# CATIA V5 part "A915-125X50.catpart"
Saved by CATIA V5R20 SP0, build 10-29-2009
Part number: A915-125X50
Source: Unknown
Property "A": "75.000"
Property "ARTICLENO": "A915-125X50"
Property "BOMINFO": "A915-125X50"
Property "CODE": "A915-125X50"
Property "CREATOR": "CADENAS GmbH"
Property "D": "13.500"
Property "D1": "20.000"
Property "FORM": "A"
Property "L": "50.000"
Property "L1": "25.000"
Property "L2": "0.000"
Property "LINA": "A915-125X50"
Property "NB": "A915-125X50"
Property "NBSYN": "$CODE."
Property "NN": "A915"
Property "NT": "VDI 3357 Wear Plates, steel"
Property "SCREW": "M12x25"
Property "SUPPLIER": "CF"
Property "T": "13.000"
Property "W": "125.000"
Bounding box of the stored display mesh (mm): x 0 to 20, y 0 to 50, z -62.5 to 62.5
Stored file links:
  C:\Users\borellobunino\Desktop\3D X SITO CF\A915\GSB_OILLESS_G22501125050\CATIAV5\A915-125X50.catpart
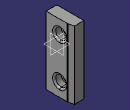
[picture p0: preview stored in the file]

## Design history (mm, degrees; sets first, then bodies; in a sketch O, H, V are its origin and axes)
Body1 "Geometry.1" (main body)
  Solid1 "A915-125X50.catpart": solid without history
